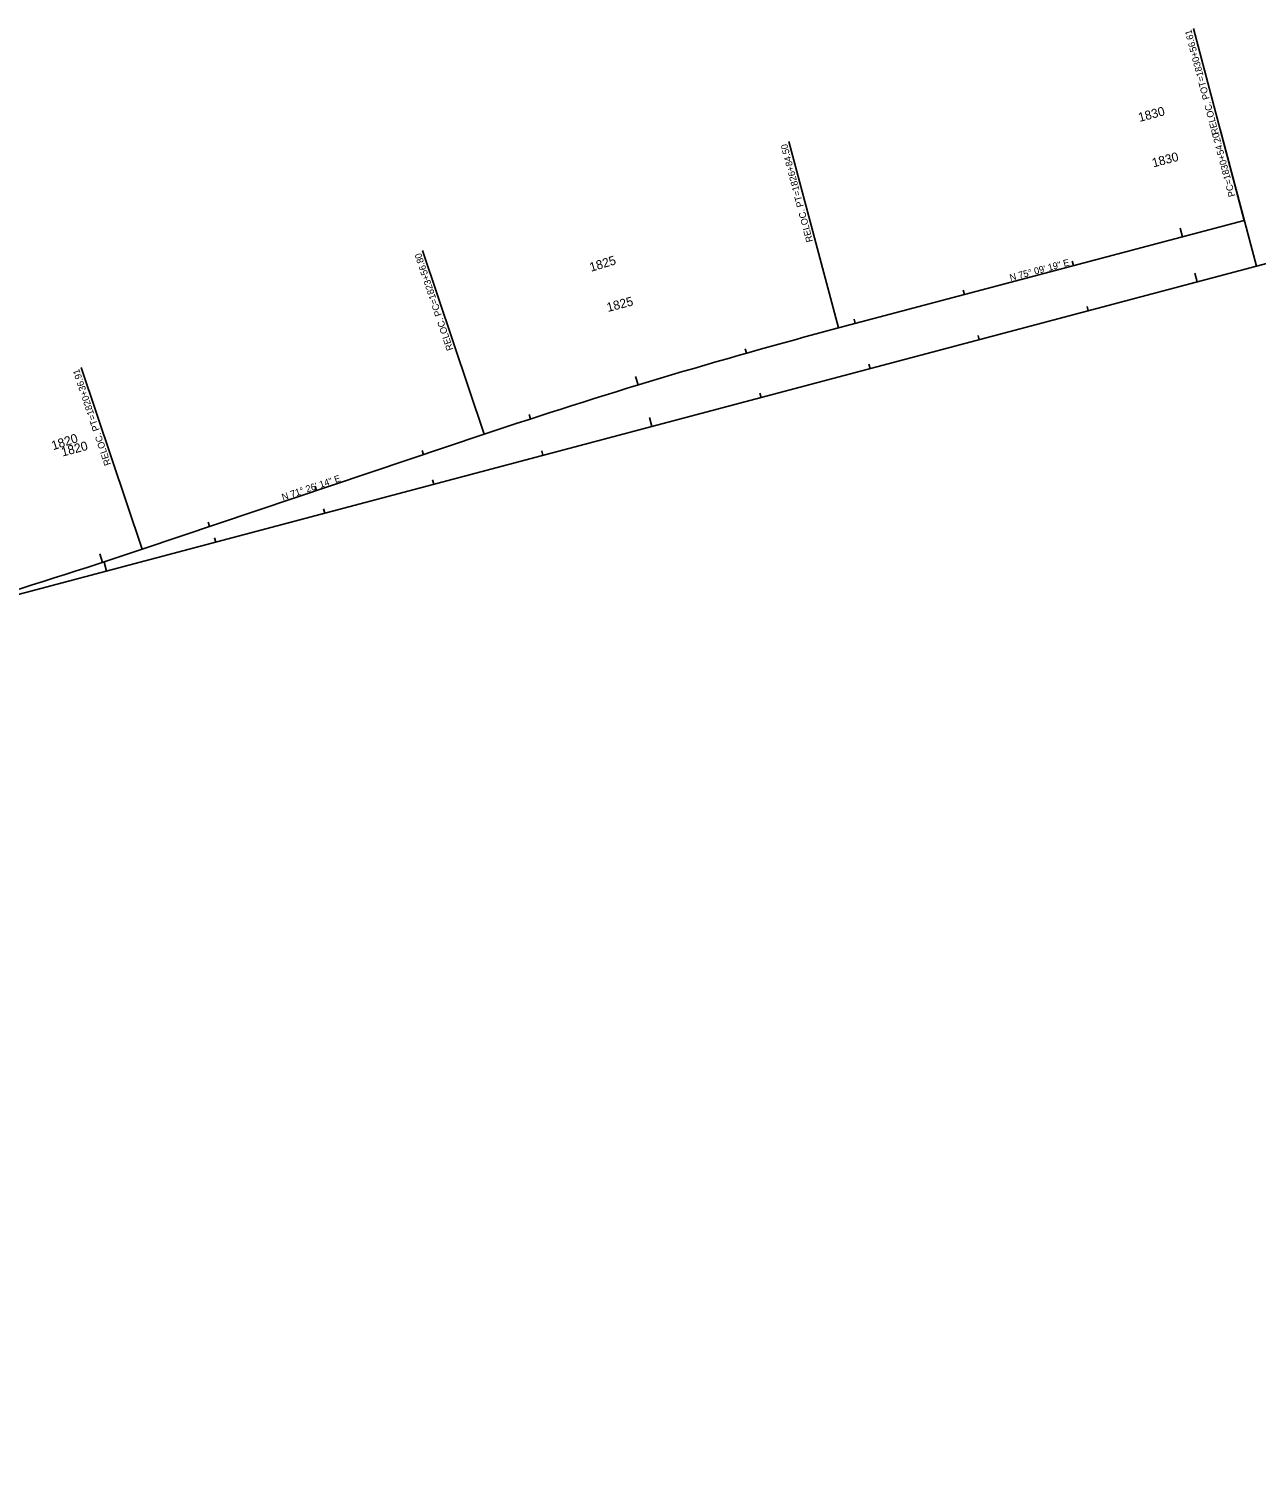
# Model space of a CAD drawing. Extents: x 2106154 to 2121963, y 864504 to 868517.
# Drawn here: x 2112990 to 2114078, y 867153 to 868421 of the extents above; entities that cross this region are included whole.
import ezdxf

# ---------------------------------------------------------------- set-up
doc = ezdxf.new("R2010")
doc.units = 0
for name, color, linetype in [('RD_HC_Cl', 7, 'Continuous'), ('RD_HC_CL_Rel', 7, 'Continuous'), ('RD_HC_Data', 7, 'Continuous'), ('RD_HC_Data_Rel', 7, 'Continuous'), ('RD_HC_Data_Tic', 7, 'Continuous'), ('RD_HC_Data_Tic_Rel', 7, 'Continuous'), ('RD_HC_TX_Rel_Sta50', 7, 'Continuous'), ('RD_HC_TX_Sta50', 7, 'Continuous')]:
    doc.layers.add(name, color=color, linetype=linetype)

msp = doc.modelspace()

# ---------------------------------------------------------------- linework, layer by layer
at = {"layer": 'RD_HC_Cl'}
msp.add_line((2110088.7, 867152.7), (2114077.7, 868210), dxfattribs=at)
msp.add_arc((2115545.6, 862671.7), 5729.6, 82.67967, 104.84478, dxfattribs=at)
at = {"layer": 'RD_HC_CL_Rel'}
for p, q in [((2113707.3, 868155.3), (2114066.9, 868250.6)), ((2113090.2, 867959.3), (2113393.4, 868061.1))]:
    msp.add_line(p, q, dxfattribs=at)
for centre, start, end in [((2115001.1, 863273.8), 104.8448, 108.5627), ((2111482.6, 872746.5), 284.8448, 288.5627)]:
    msp.add_arc(centre, 5050, start, end, dxfattribs=at)
at = {"layer": 'RD_HC_Data'}
msp.add_line((2114077.7, 868210), (2114045.6, 868331.3), dxfattribs=at)
at = {"layer": 'RD_HC_Data_Rel'}
for p, q in [((2114066.9, 868250.6), (2114021.9, 868420.5)), ((2113707.3, 868155.3), (2113663.4, 868320.6)), ((2113393.4, 868061.1), (2113338.7, 868224)), ((2113090.2, 867959.3), (2113036.2, 868120.1))]:
    msp.add_line(p, q, dxfattribs=at)
at = {"layer": 'RD_HC_Data_Tic'}
for p, q in [((2114025.3, 868196.1), (2114023.3, 868203.9)), ((2113928.7, 868170.5), (2113927.6, 868174.4)), ((2113832, 868144.9), (2113831, 868148.7)), ((2113735.3, 868119.3), (2113734.3, 868123.1)), ((2113638.7, 868093.6), (2113637.6, 868097.5)), ((2113542, 868068), (2113540, 868075.8)), ((2113445.3, 868042.4), (2113444.3, 868046.3)), ((2113348.7, 868016.8), (2113347.7, 868020.6)), ((2113252, 867991.2), (2113251, 867995)), ((2113155.4, 867965.5), (2113154.3, 867969.4)), ((2113058.7, 867939.9), (2113056.6, 867947.7))]:
    msp.add_line(p, q, dxfattribs=at)
at = {"layer": 'RD_HC_Data_Tic_Rel'}
for p, q in [((2114012.2, 868236.1), (2114010.2, 868243.8)), ((2113915.6, 868210.5), (2113914.5, 868214.4)), ((2113818.9, 868184.9), (2113817.9, 868188.7)), ((2113722.2, 868159.2), (2113721.2, 868163.1)), ((2113625.8, 868132.9), (2113624.7, 868136.8)), ((2113529.8, 868104.8), (2113527.5, 868112.4)), ((2113434.5, 868074.7), (2113433.2, 868078.5)), ((2113339.6, 868043), (2113338.3, 868046.8)), ((2113244.8, 868011.2), (2113243.5, 868015)), ((2113150, 867979.4), (2113148.7, 867983.1)), ((2113055.2, 867947.6), (2113052.7, 867955.2))]:
    msp.add_line(p, q, dxfattribs=at)

# ---------------------------------------------------------------- texts
at = {"layer": 'RD_HC_Data'}
msp.add_text('PC=1830+54.20', height=6, rotation=104.8448, dxfattribs=at).set_placement((2114059.1, 868272.3))
at = {"layer": 'RD_HC_Data_Rel'}
for s, rotation, p in [('RELOC. POT=1830+56.61', 104.8448, (2114044.5, 868327.4)), ('RELOC. PT=1826+84.50', 104.8448, (2113684.8, 868232.1)), ('RELOC. PC=1823+56.80', 108.5627, (2113366.1, 868136.3)), ('N 75%%d 09\' 19" E', 14.8448, (2113859.9, 868196.8)), ('N 75%%d 09\' 19" E', 14.8448, (2113859.9, 868196.8)), ('RELOC. PT=1820+36.91', 108.5627, (2113062.8, 868034.5)), ('N 71%%d 26\' 14" E', 18.5627, (2113215.1, 868002.3)), ('N 71%%d 26\' 14" E', 18.5627, (2113215.1, 868002.3))]:
    msp.add_text(s, height=6, rotation=rotation, dxfattribs=at).set_placement(p)
at = {"layer": 'RD_HC_TX_Rel_Sta50'}
for s, rotation, p in [('1830', 14.8448, (2113974.2, 868337.8)), ('1825', 16.938, (2113488.1, 868205)), ('1820', 18.1439, (2113011.4, 868046.9))]:
    msp.add_text(s, height=8, rotation=rotation, dxfattribs=at).set_placement(p)
at = {"layer": 'RD_HC_TX_Sta50'}
for s, p in [('1830', (2113986.4, 868297.5)), ('1825', (2113503.1, 868169.4)), ('1820', (2113019.7, 868041.3))]:
    msp.add_text(s, height=8, rotation=14.8448, dxfattribs=at).set_placement(p)

doc.saveas('drawing.dxf')
